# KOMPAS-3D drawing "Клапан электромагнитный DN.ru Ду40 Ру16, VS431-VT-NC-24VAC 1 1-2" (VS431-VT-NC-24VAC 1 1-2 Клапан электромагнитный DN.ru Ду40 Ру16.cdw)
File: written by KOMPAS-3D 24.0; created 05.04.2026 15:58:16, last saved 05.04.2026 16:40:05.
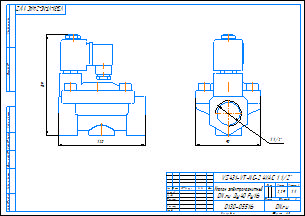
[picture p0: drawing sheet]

Document properties: c3d_UniqueCompID: ef56311e-7521-43dc-8291-0e6108b3d81d; Автор: artio; Класс точности: c; Знак неуказанной шероховатости: Шероховатость не задана; Рассекать на разрезах: Да; c3d_UniqueCompID: ef56311e-7521-43dc-8291-0e6108b3d81d; Автор: artio; Класс точности: c; Знак неуказанной шероховатости: Шероховатость не задана; Рассекать на разрезах: Да; c3d_UniqueCompID: ef56311e-7521-43dc-8291-0e6108b3d81d; Автор: artio; Класс точности: c; Знак неуказанной шероховатости: Шероховатость не задана; Рассекать на разрезах: Да; c3d_UniqueCompID: ef56311e-7521-43dc-8291-0e6108b3d81d; Автор: artio; Класс точности: c; Знак неуказанной шероховатости: Шероховатость не задана; Рассекать на разрезах: Да; Автор: artio; Форматы листов документа: A3; Полное имя файла: VS431-VT-NC-24VAC 1 1-2 Клапан электромагнитный DN.ru Ду40 Ру16.m3d; Масса: 2.285; Наименование: Клапан электромагнитный DN.ru Ду40 Ру16; Количество листов документа: 1; Примечание: D130-05516

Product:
- Body: Тело 1  | qty 1
    Масса: 3.859459
- Part/product: Клапан электромагнитный DN.ru Ду40 Ру16  | designation VS431-VT-NC-24VAC 1 1-2
    Масса: 2.285
    Раздел спецификации: Прочие изделия
    Примечание: D130-05516
    additional columns: ef56311e-7521-43dc-8291-0e6108b3d81d; artio; c; Шероховатость не задана; Да

Views: Вид 1, Спереди
Referenced files in C:\Users\artio\OneDrive\Рабочий стол\Клапан электромагнитный DN.ru\VS431\VS431-ET-NC\: VS431-ET-NC-24VAC 3-4 Клапан электромагнитный DN.ru Ду20 Ру16.m3d, VS431-ET-NC-24VAC 3-4 Клапан электромагнитный DN.ru Ду20 Ру16.cdw
Referenced files in C:\Users\artio\OneDrive\Рабочий стол\Клапан электромагнитный DN.ru\VS431\VS431-VT-NC\: VS431-VT-NC-24VAC 1 1-2 Клапан электромагнитный DN.ru Ду40 Ру16.m3d
Referenced files in C:\Users\artio\OneDrive\Рабочий стол\Клапан электромагнитный DN.ru\VS431\VS431-VT-NC\VS431-VT-NC-24VAC\Ду40\: VS431-VT-NC-24VAC 1 1-2 Клапан электромагнитный DN.ru Ду40 Ру16.m3d
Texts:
  VS431-VT-NC-24VAC 1 1-2
  Клапан электромагнитный
  DN.ru Ду40 Ру16
  VS431-VT-NC-24VAC 1 1/2"
  VS431-VT-NC-24VAC 1 1/2"-
  Клапан электромагнитный DN.ru Ду40 Ру16
  VS431-VT-NC-24VAC 1 1-2 Клапан электромагнитный DN.ru Ду40 Ру16
Dimensions and other numbers on the sheet: 0; 3; 2; 4; 90; 1 1/2"; 1:1; 1; 2,29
